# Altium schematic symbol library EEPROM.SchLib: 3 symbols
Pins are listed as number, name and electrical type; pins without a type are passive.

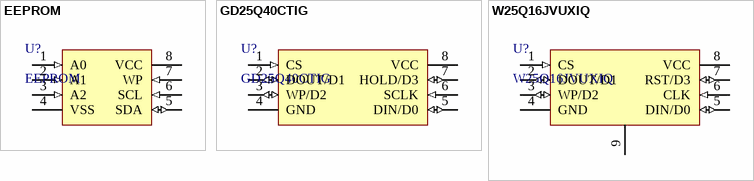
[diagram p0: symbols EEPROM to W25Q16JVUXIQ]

## EEPROM
designator U?
footprint TSSOP-8
pins: 1 A0 (in), 2 A1 (in), 3 A2 (in), 4 VSS (power), 5 SDA (io), 6 SCL (in), 7 WP (in), 8 VCC (power)

## GD25Q40CTIG
designator U?
footprint USON-2X3 (SON, 8-Leads, Body 2.00x3.00mm, Pitch 0.50mm, IPC Medium Density)
footprint SO-8-N
pins: 1 CS (in), 2 DOUT/D1 (io), 3 WP/D2 (io), 4 GND (power), 5 DIN/D0 (io), 6 SCLK (in), 7 HOLD/D3 (io), 8 VCC (power)

## W25Q16JVUXIQ
designator U?
footprint USON-2X3 (SON, 8-Leads, Body 2.00x3.00mm, Pitch 0.50mm, IPC Medium Density)
pins: 1 CS (in), 2 DOUT/D1 (io), 3 WP/D2 (io), 4 GND (power), 5 DIN/D0 (io), 6 CLK (in), 7 RST/D3 (io), 8 VCC (power), 9 GND (power)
